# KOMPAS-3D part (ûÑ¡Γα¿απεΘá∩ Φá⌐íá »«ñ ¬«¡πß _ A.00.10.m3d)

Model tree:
1. Эскиз:1
2. Операция выдавливания:1
     Расстояние 1 = 12
3. Отверстие:1
     Глубина выреза = 12; Диаметр отверстия = 14; Угол конуса торца = 118; Диаметр зенковки = 25; Глубина зенковки = 9.52628; Угол зенковки = 60

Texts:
  Центрирующая шайба под конус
